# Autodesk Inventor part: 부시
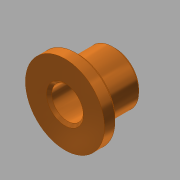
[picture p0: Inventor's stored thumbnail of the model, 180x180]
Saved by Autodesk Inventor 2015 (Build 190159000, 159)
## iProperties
Created: 2016-02
Part Number: 부시
Material: 스테인리스강
Document SubType Name: Modeling
Designer: mduedu
Density: 8.08 g/cm^3
Appearance: 금속 1600F 열
Mass: 45.9536 g
Surface Area: 31.3929 cm^2
Volume: 5.68733 cm^3
Author: mduedu
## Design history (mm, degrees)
sketch "스케치1"
  geometry: C1 r 15 at (0, 0); 1 further point
  constraints: 1 centre point, 1 coincident
  dimensions: "d0" = 30 diameter of C1
extrude "돌출1" new body sketch "스케치1" distance "d1" = 5; taper "d2" = 0 deg
sketch "스케치2"
  geometry: C1 r 10 at (0, 0); 1 further point
  constraints: 1 centre point, 1 coincident
  dimensions: "d3" = 20 diameter of C1
extrude "돌출2" join sketch "스케치2" distance "d4" = 14; taper "d5" = 0 deg
hole "구멍1" diameter "d8" = 12; stored, may be unused: countersink angle "d12" = 90 deg, drill point angle "d14" = 118 deg; dims "d9" = 6, "d10" = 4, "d11" = 2, "d13" = 8, "d15" = 10, "d16" = 10
chamfer "모따기1" distance "d17" = 1; stored, may be unused: second distance "d18" = 2, angle "d19" = 45 deg
chamfer "모따기2" distance "d20" = 1; stored, may be unused: second distance "d21" = 2, angle "d22" = 45 deg
chamfer "모따기3" distance "d23" = 1; stored, may be unused: second distance "d24" = 2, angle "d25" = 45 deg
node "솔리드1"
